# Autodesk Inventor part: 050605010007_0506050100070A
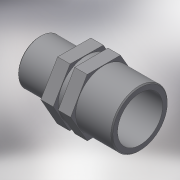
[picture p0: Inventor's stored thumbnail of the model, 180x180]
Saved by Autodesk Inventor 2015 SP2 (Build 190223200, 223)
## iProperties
Created: 2017-05
Part Number: 050605010007_0506050100070A
Material: Generic
Description: PLASSON REDUCING NIPPLE 1"-3/4"
Document SubType Name: Modeling
Designer: KIM
Density: 1 g/cm^3
Appearance: Default
Author: KIM
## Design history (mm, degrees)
derived "050605.ipt"
feature "Solid1::050605.ipt"
tag "TaggingFeature1"
body "Solid1"
other parameters: "d1" = 33.249, "d5" = 19, "d6" = 5, "d8" = 0.5, "d12" = 0, "d14" = 26.441, "d15" = 21.1528, "d16" = 26.5992, "d17" = 17, "d18" = 2.5, "d19" = 36, "d21" = 0, "R_" = 33.249, "E_" = 36, "l_" = 19, "R_1" = 26.441, "l_1" = 17
